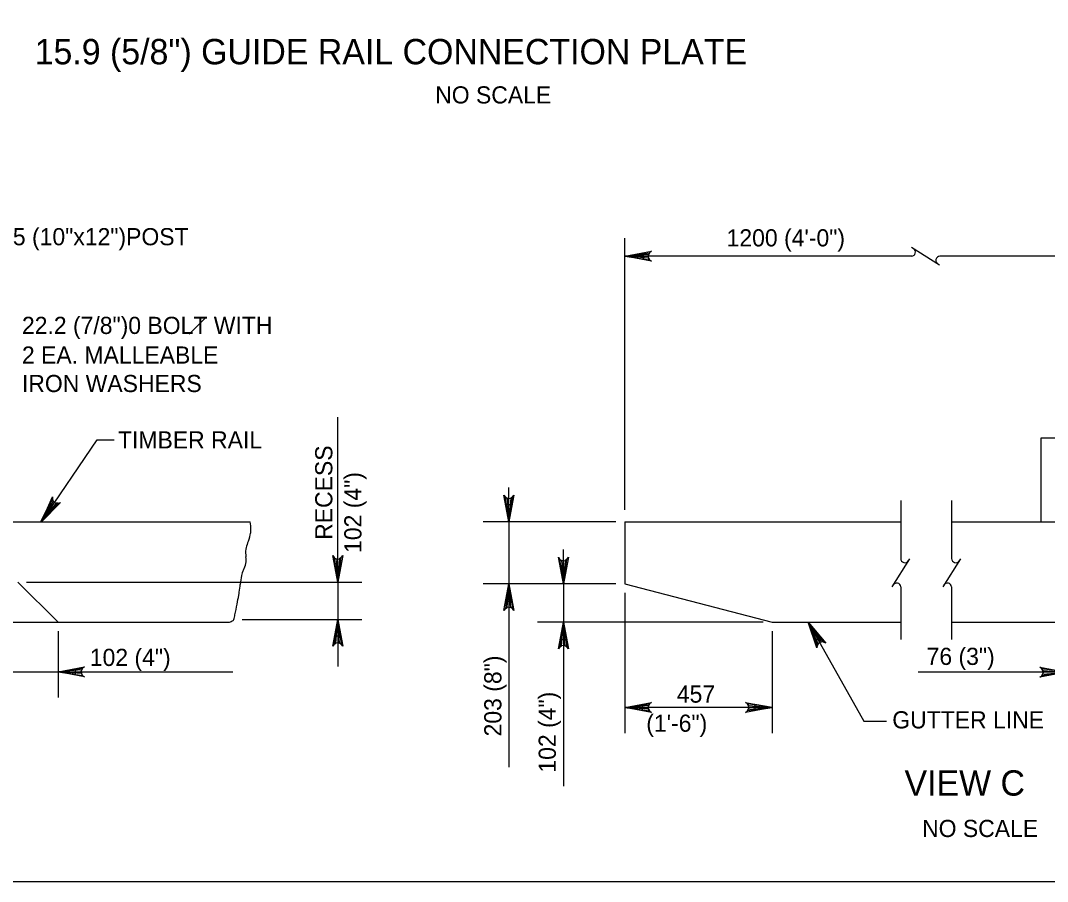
# Model space of a CAD drawing. Extents: x 0 to 36.3, y -66 to 0.
# Drawn here: x 13.18 to 20.36, y -21.25 to -15.23 of the extents above; entities that cross this region are included whole.
import ezdxf

# ---------------------------------------------------------------- set-up
doc = ezdxf.new("R2010")
doc.units = 0
for name, color, linetype in [('1', 7, 'Continuous'), ('2', 7, 'Continuous'), ('3', 7, 'Continuous')]:
    doc.layers.add(name, color=color, linetype=linetype)

msp = doc.modelspace()

# ---------------------------------------------------------------- linework, layer by layer
at = {"layer": '1'}
msp.add_lwpolyline([(1.75, -21.25), (33.25, -21.25), (33.25, -0.75), (1.75, -0.75)], close=True, dxfattribs=at)
at = {"layer": '2'}
for p, q in [((19.6036, -16.9415), (19.408, -16.8187)), ((19.4084, -16.8801), (17.4027, -16.8801)), ((20.6658, -16.8801), (19.6058, -16.8801)), ((20.3143, -18.1498), (21.0173, -18.1498)), ((20.3143, -18.7356), (20.3143, -18.1498)), ((19.332, -18.5877), (19.332, -18.9929)), ((19.6874, -18.5877), (19.6874, -18.9929)), ((9.842, -18.7351), (14.7836, -18.7351)), ((17.4027, -18.7356), (19.332, -18.7356)), ((17.4027, -18.7356), (17.4027, -19.1706)), ((19.6874, -18.7356), (22.3305, -18.7356)), ((19.3935, -18.9952), (19.2706, -19.1907)), ((19.7489, -18.9952), (19.626, -19.1907)), ((13.439, -19.4385), (13.1592, -19.1587)), ((17.4027, -19.1706), (18.4319, -19.4385)), ((19.332, -19.1902), (19.332, -19.5587)), ((19.6874, -19.1902), (19.6874, -19.5587)), ((7.728, -19.4385), (13.439, -19.4385)), ((13.439, -19.4385), (14.6374, -19.4385)), ((18.4319, -19.4385), (19.332, -19.4385)), ((19.6874, -19.4385), (22.1845, -19.4385))]:
    msp.add_line(p, q, dxfattribs=at)
for centre, radius, start, end in [((19.4057, -16.8514), 0.0289, 275.32859, 57.86724), ((19.6058, -16.909), 0.0289, 90, 240), ((14.3792, -18.792), 0.4083, 0, 8.01238), ((14.6284, -18.792), 0.1591, 347.1491, 0), ((14.9314, -18.9557), 0.1809, 157.02806, 170.99701), ((14.4484, -18.7509), 0.3437, 337.02806, 347.1491), ((14.9096, -18.9522), 0.1589, 170.99701, 190.43044), ((14.5935, -18.9933), 0.1629, 330.90022, 347.91871), ((14.6366, -19.0025), 0.1188, 347.91871, 10.43044), ((19.3609, -18.9929), 0.0289, 180, 330), ((19.7163, -18.9929), 0.0289, 180, 330), ((14.843, -19.1321), 0.1227, 150.90022, 170.53428), ((15.597, -19.2578), 0.8871, 170.53428, 174.54526), ((19.3033, -19.193), 0.0289, 5.32859, 147.86724), ((19.6587, -19.193), 0.0289, 5.32859, 147.86724), ((10.1252, -18.4161), 4.6526, 349.69526, 349.95839), ((14.0386, -19.109), 0.6784, 349.9584, 354.54526), ((12.1966, -18.8544), 2.5362, 347.90537, 349.60825), ((-27.1654, -11.636), 42.5547, 349.60825, 349.69526), ((14.1488, -19.2728), 0.5397, 344.21336, 347.90537), ((14.5833, -19.2955), 0.1529, 290.70356, 301.64147), ((14.658, -19.4167), 0.0105, 301.64147, 344.21336)]:
    msp.add_arc(centre, radius, start, end, dxfattribs=at)
at = {"layer": '3'}
for p, q in [((17.4027, -18.6534), (17.4027, -16.7536)), ((14.3564, -17.4242), (14.4747, -17.3058)), ((15.3949, -19.1587), (15.3949, -18.004)), ((13.3238, -18.7351), (13.7117, -18.1632)), ((13.7117, -18.1632), (13.8317, -18.1632)), ((16.5924, -18.7356), (16.5924, -18.4956)), ((17.3402, -18.7356), (16.4124, -18.7356)), ((16.5924, -18.7356), (16.5924, -20.4508)), ((15.3949, -19.1587), (15.3949, -18.9336)), ((16.9728, -19.1706), (16.9728, -18.9306)), ((13.2177, -19.1587), (15.5637, -19.1587)), ((15.3949, -19.1587), (15.3949, -19.7466)), ((17.3402, -19.1706), (16.4124, -19.1706)), ((17.3402, -19.1706), (16.7928, -19.1706)), ((16.9728, -19.1706), (16.9728, -20.5846)), ((17.4027, -19.2331), (17.4027, -20.2131)), ((16.5924, -19.2906), (16.5924, -19.4106)), ((14.7268, -19.4196), (15.5637, -19.4196)), ((18.3694, -19.4385), (16.7928, -19.4385)), ((18.6853, -19.4385), (19.0745, -20.1307)), ((13.439, -19.501), (13.439, -19.9642)), ((18.4319, -19.501), (18.4319, -20.2131)), ((16.9728, -19.5585), (16.9728, -19.6785)), ((13.0833, -19.7843), (14.6616, -19.7843)), ((20.2651, -19.7876), (19.4535, -19.7876)), ((20.4901, -19.7876), (20.2651, -19.7876)), ((18.4319, -20.0331), (17.4027, -20.0331)), ((19.0745, -20.1307), (19.2331, -20.1307))]:
    msp.add_line(p, q, dxfattribs=at)
for points in [[(17.4027, -16.8801), (17.5891, -16.8452), (17.5747, -16.8551), (17.5673, -16.8676), (17.5652, -16.8801), (17.5673, -16.8926), (17.5747, -16.9051), (17.5891, -16.915), (17.4027, -16.8801), (17.5747, -16.9051), (17.5673, -16.8926), (17.4027, -16.8801), (17.5652, -16.8801), (17.5673, -16.8676), (17.4027, -16.8801), (17.5747, -16.8551)], [(13.3238, -18.7351), (13.3995, -18.5612), (13.3997, -18.5787), (13.4058, -18.5918), (13.415, -18.6006), (13.4265, -18.6058), (13.441, -18.6067), (13.4573, -18.6004), (13.3238, -18.7351), (13.441, -18.6067), (13.4265, -18.6058), (13.3238, -18.7351), (13.415, -18.6006), (13.4058, -18.5918), (13.3238, -18.7351), (13.3997, -18.5787)], [(16.5924, -18.7356), (16.5575, -18.5492), (16.5674, -18.5635), (16.5799, -18.5709), (16.5924, -18.5731), (16.6049, -18.5709), (16.6174, -18.5635), (16.6273, -18.5492), (16.5924, -18.7356), (16.6174, -18.5635), (16.6049, -18.5709), (16.5924, -18.7356), (16.5924, -18.5731), (16.5799, -18.5709), (16.5924, -18.7356), (16.5674, -18.5635)], [(15.3949, -19.1587), (15.36, -18.9722), (15.3699, -18.9866), (15.3824, -18.994), (15.3949, -18.9962), (15.4074, -18.994), (15.4199, -18.9866), (15.4298, -18.9722), (15.3949, -19.1587), (15.4199, -18.9866), (15.4074, -18.994), (15.3949, -19.1587), (15.3949, -18.9962), (15.3824, -18.994), (15.3949, -19.1587), (15.3699, -18.9866)], [(16.9728, -19.1706), (16.9379, -18.9842), (16.9478, -18.9985), (16.9603, -19.0059), (16.9728, -19.0081), (16.9853, -19.0059), (16.9978, -18.9985), (17.0077, -18.9842), (16.9728, -19.1706), (16.9978, -18.9985), (16.9853, -19.0059), (16.9728, -19.1706), (16.9728, -19.0081), (16.9603, -19.0059), (16.9728, -19.1706), (16.9478, -18.9985)], [(16.5924, -19.1706), (16.6273, -19.357), (16.6174, -19.3427), (16.6049, -19.3352), (16.5924, -19.3331), (16.5799, -19.3352), (16.5674, -19.3427), (16.5575, -19.357), (16.5924, -19.1706), (16.5674, -19.3427), (16.5799, -19.3352), (16.5924, -19.1706), (16.5924, -19.3331), (16.6049, -19.3352), (16.5924, -19.1706), (16.6174, -19.3427)], [(15.3949, -19.4196), (15.4298, -19.606), (15.4199, -19.5917), (15.4074, -19.5843), (15.3949, -19.5821), (15.3824, -19.5843), (15.3699, -19.5917), (15.36, -19.606), (15.3949, -19.4196), (15.3699, -19.5917), (15.3824, -19.5843), (15.3949, -19.4196), (15.3949, -19.5821), (15.4074, -19.5843), (15.3949, -19.4196), (15.4199, -19.5917)], [(16.9728, -19.4385), (17.0077, -19.6249), (16.9978, -19.6106), (16.9853, -19.6032), (16.9728, -19.601), (16.9603, -19.6032), (16.9478, -19.6106), (16.9379, -19.6249), (16.9728, -19.4385), (16.9478, -19.6106), (16.9603, -19.6032), (16.9728, -19.4385), (16.9728, -19.601), (16.9853, -19.6032), (16.9728, -19.4385), (16.9978, -19.6106)], [(18.6853, -19.4385), (18.8072, -19.5838), (18.7914, -19.5762), (18.7769, -19.5759), (18.765, -19.5802), (18.7552, -19.5882), (18.7478, -19.6007), (18.7462, -19.6181), (18.6853, -19.4385), (18.7478, -19.6007), (18.7552, -19.5882), (18.6853, -19.4385), (18.765, -19.5802), (18.7769, -19.5759), (18.6853, -19.4385), (18.7914, -19.5762)], [(13.439, -19.7843), (13.6254, -19.7493), (13.6111, -19.7592), (13.6037, -19.7718), (13.6015, -19.7843), (13.6037, -19.7967), (13.6111, -19.8092), (13.6254, -19.8192), (13.439, -19.7843), (13.6111, -19.8092), (13.6037, -19.7967), (13.439, -19.7843), (13.6015, -19.7843), (13.6037, -19.7718), (13.439, -19.7843), (13.6111, -19.7592)], [(20.4901, -19.7876), (20.3037, -19.8225), (20.318, -19.8126), (20.3254, -19.8001), (20.3276, -19.7876), (20.3254, -19.7751), (20.318, -19.7626), (20.3037, -19.7527), (20.4901, -19.7876), (20.318, -19.7626), (20.3254, -19.7751), (20.4901, -19.7876), (20.3276, -19.7876), (20.3254, -19.8001), (20.4901, -19.7876), (20.318, -19.8126)], [(17.4027, -20.0331), (17.5891, -19.9982), (17.5747, -20.0081), (17.5673, -20.0206), (17.5652, -20.0331), (17.5673, -20.0456), (17.5747, -20.0581), (17.5891, -20.068), (17.4027, -20.0331), (17.5747, -20.0581), (17.5673, -20.0456), (17.4027, -20.0331), (17.5652, -20.0331), (17.5673, -20.0206), (17.4027, -20.0331), (17.5747, -20.0081)], [(18.4319, -20.0331), (18.2455, -20.068), (18.2598, -20.0581), (18.2673, -20.0456), (18.2694, -20.0331), (18.2673, -20.0206), (18.2598, -20.0081), (18.2455, -19.9982), (18.4319, -20.0331), (18.2598, -20.0081), (18.2673, -20.0206), (18.4319, -20.0331), (18.2694, -20.0331), (18.2673, -20.0456), (18.4319, -20.0331), (18.2598, -20.0581)]]:
    msp.add_lwpolyline(points, dxfattribs=at)
for points in [[(17.5308, -16.8588), (17.5308, -16.9014), (17.4027, -16.8801)], [(13.4051, -18.6507), (13.373, -18.6268), (13.3174, -18.7351)], [(16.5724, -18.6156), (16.6124, -18.6156), (16.5924, -18.7356)], [(15.3761, -19.0461), (15.4137, -19.0461), (15.3949, -19.1587)], [(16.9528, -19.0506), (16.9928, -19.0506), (16.9728, -19.1706)], [(16.5724, -19.2906), (16.6124, -19.2906), (16.5924, -19.1706)], [(15.3761, -19.5321), (15.4137, -19.5321), (15.3949, -19.4196)], [(16.9528, -19.5585), (16.9928, -19.5585), (16.9728, -19.4385)], [(18.7347, -19.5647), (18.7672, -19.5459), (18.6946, -19.4579)], [(13.559, -19.7643), (13.559, -19.8042), (13.439, -19.7843)], [(17.5227, -20.0131), (17.5227, -20.0531), (17.4027, -20.0331)], [(18.3119, -20.0131), (18.3119, -20.0531), (18.4319, -20.0331)]]:
    msp.add_lwpolyline(points, close=True, dxfattribs=at)

# ---------------------------------------------------------------- texts
at = {"layer": '2'}
for s, height, p in [('15.9 (5/8") GUIDE RAIL CONNECTION PLATE', 0.177167, (13.2758, -15.5381)), ('VIEW C', 0.17717, (19.3582, -20.6502))]:
    msp.add_text(s, height=height, dxfattribs=at).set_placement(p)
at = {"layer": '3'}
for s, p in [('NO SCALE', (16.0764, -15.8119)), ('C 254x305 (10"x12")POST', (12.4365, -16.803)), ('1200 (4\'-0")', (18.1142, -16.811)), ('22.2 (7/8")0 BOLT WITH', (13.1868, -17.423)), ('2 EA. MALLEABLE', (13.1868, -17.6302)), ('IRON WASHERS', (13.1868, -17.8292)), ('TIMBER RAIL', (13.8585, -18.2233)), ('102 (4")', (13.6614, -19.7438)), ('76 (3")', (19.5127, -19.7365)), ('457', (17.7661, -20.0002)), ('(1\'-6")', (17.5525, -20.2036)), ('GUTTER LINE', (19.2727, -20.1803)), ('NO SCALE', (19.4811, -20.9394))]:
    msp.add_text(s, height=0.12, dxfattribs=at).set_placement(p)
for s, p in [('RECESS', (15.3575, -18.8621)), ('102 (4")', (15.5608, -18.9537)), ('203 (8")', (16.5395, -20.2362)), ('102 (4")', (16.9199, -20.4892))]:
    msp.add_text(s, height=0.12, rotation=90, dxfattribs=at).set_placement(p)

doc.saveas('drawing.dxf')
